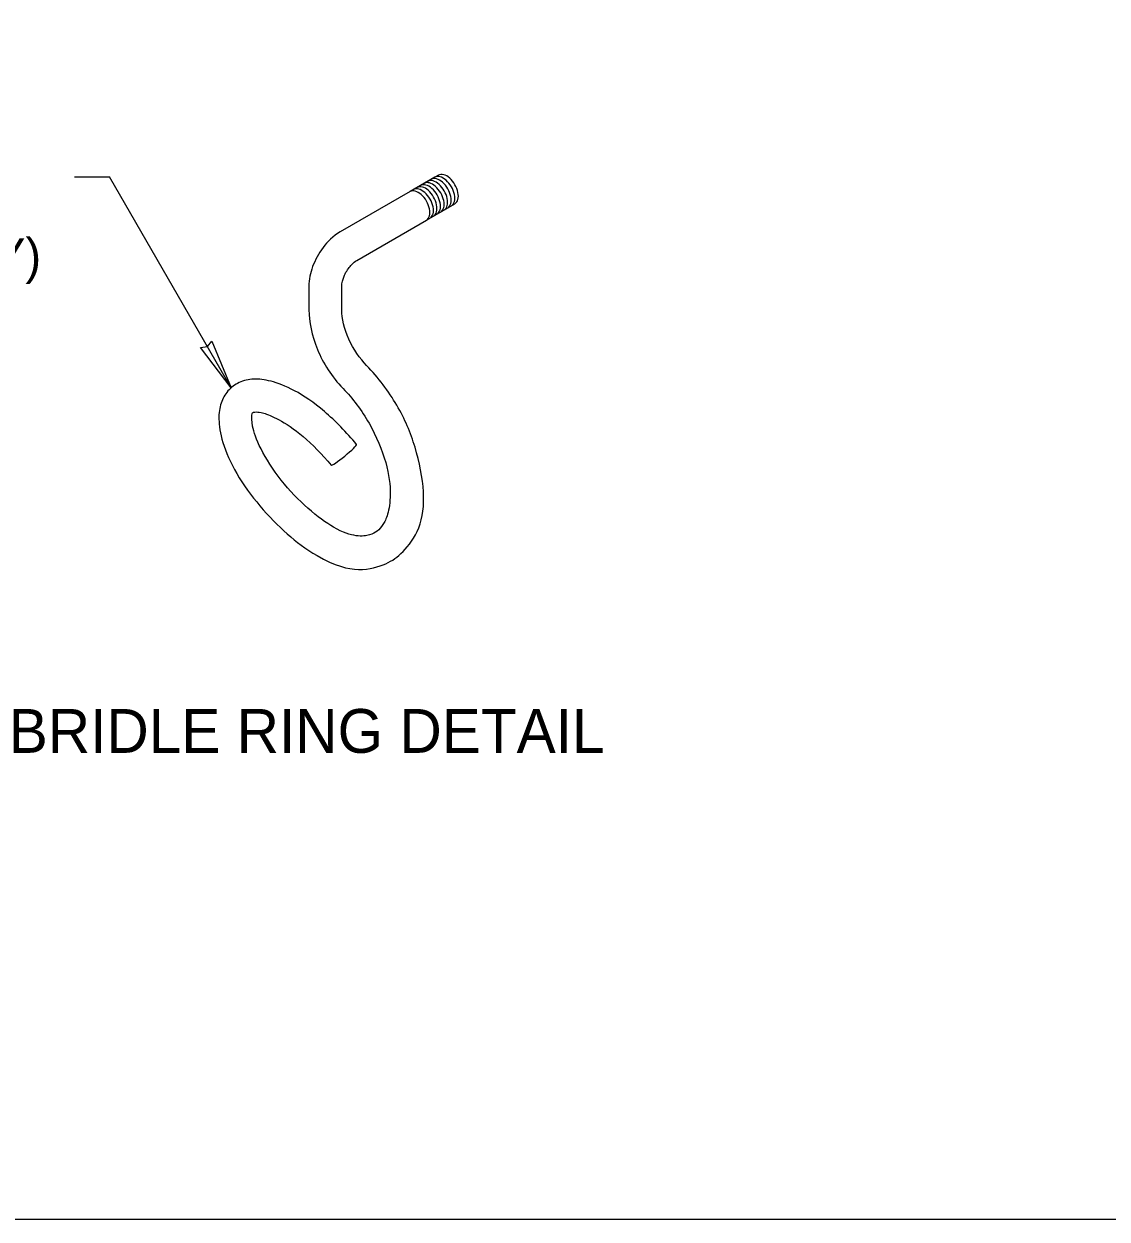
# Model space of a CAD drawing. Extents: x 99862 to 103151, y 100000 to 105076.
# Drawn here: x 101110 to 101605, y 103000 to 103545 of the extents above; entities that cross this region are included whole.
import ezdxf

# ---------------------------------------------------------------- set-up
doc = ezdxf.new("R2010")
doc.units = 0
for name, color, linetype in [('Level 1', 7, 'Continuous'), ('Level 15', 7, 'Continuous'), ('Level 20', 7, 'Continuous'), ('Level 8', 7, 'Continuous')]:
    doc.layers.add(name, color=color, linetype=linetype)

msp = doc.modelspace()

# ---------------------------------------------------------------- linework, layer by layer
at = {"layer": 'Level 1'}
msp.add_lwpolyline([(99862, 102999.5), (103151, 102999.5), (103151, 105075.5), (99862, 105075.5)], close=True, dxfattribs=at)
at = {"layer": 'Level 15'}
for p in [(101133.54, 103475.08), (101205.08, 103378.87)]:
    msp.add_line(p, (101149.54, 103475.08), dxfattribs=at)
msp.add_lwpolyline([(101205.08, 103378.87), (101191.08, 103397.15), (101194.19, 103397.73), (101196.25, 103400.14)], close=True, dxfattribs=at)
at = {"layer": 'Level 8'}
for p, q in [((101298.05, 103474.89), (101286.68, 103468.33)), ((101299.67, 103475.83), (101298.05, 103474.89)), ((101286.68, 103468.33), (101254.86, 103449.95)), ((101294.18, 103455.33), (101307.17, 103462.83)), ((101262.36, 103436.96), (101294.18, 103455.33)), ((101240.51, 103425.09), (101240.51, 103414.35)), ((101255.51, 103414.35), (101255.51, 103425.09))]:
    msp.add_line(p, q, dxfattribs=at)
for centre, major_axis, ratio, start_param, end_param in [((101303.42, 103469.33), (3.75, -6.5), 0.57735, 6.283112, 9.424778), ((101295.3, 103464.64), (3.75, -6.5), 0.57735, 6.283112, 9.424778), ((101296.93, 103465.58), (3.75, -6.5), 0.57735, 6.283112, 9.424778), ((101298.55, 103466.52), (3.75, -6.5), 0.57735, 6.283112, 9.424778), ((101300.17, 103467.45), (3.75, -6.5), 0.57735, 6.283112, 9.424778), ((101301.8, 103468.39), (3.75, -6.5), 0.57735, 6.283112, 9.424778), ((101290.43, 103461.83), (3.75, -6.5), 0.57735, 6.283112, 9.424778), ((101290.43, 103461.83), (3.75, -6.5), 0.57735, 3.141593, 3.141605), ((101292.06, 103462.77), (3.75, -6.5), 0.57735, 6.283112, 9.424778), ((101293.68, 103463.7), (3.75, -6.5), 0.57735, 6.283112, 9.424778), ((101248.01, 103414.35), (7.5, 0), 0.57735, 3.141593, 3.141703), ((101256.45, 103348.22), (5.81, 4.74), 0.091752, 3.1416, 6.283185), ((101256.45, 103348.22), (5.81, 4.74), 0.091752, 3.141585, 3.1416)]:
    msp.add_ellipse(centre, major_axis=major_axis, ratio=ratio, start_param=start_param, end_param=end_param, dxfattribs=at)
for points in [[(101254.86, 103449.95), (101251.44, 103447.98), (101246.61, 103443.24), (101241.71, 103433.99), (101240.51, 103428.3), (101240.51, 103425.09)], [(101255.51, 103425.09), (101255.5, 103426.51), (101256.52, 103430.46), (101259.77, 103435.05), (101261.65, 103436.56), (101262.36, 103436.96)], [(101240.51, 103414.35), (101240.51, 103409.12), (101243.16, 103396.14), (101250.89, 103383.89), (101256.13, 103378.51)], [(101266.88, 103388.97), (101263.82, 103392.12), (101257.83, 103400.86), (101255.5, 103410.45), (101255.51, 103414.35)], [(101244.26, 103302.24), (101252.45, 103297.51), (101263.94, 103294.56), (101276.63, 103298.45), (101283.13, 103302.99), (101291.7, 103314.11), (101293.9, 103330.43), (101289.53, 103352.26), (101281.74, 103370.73), (101272.15, 103383.56), (101266.88, 103388.97)], [(101262.26, 103352.96), (101257.77, 103358.45), (101247.37, 103369.07), (101233.45, 103378.37), (101222.74, 103382.3), (101215.2, 103383.17), (101208.49, 103381.61), (101203.24, 103377.64), (101200.07, 103371.98), (101199.05, 103365.08), (101200.44, 103354.53), (101206.83, 103339.68), (101217.91, 103324.6), (101230.71, 103311.53), (101238.94, 103305.31), (101244.26, 103302.24)], [(101256.13, 103378.51), (101260.49, 103374.03), (101268.72, 103363.03), (101276.62, 103344.04), (101278.18, 103329.34), (101276.51, 103320.43), (101274.39, 103316.12), (101271.78, 103313.28), (101268.71, 103311.53), (101262.73, 103310.69), (101256.15, 103312.7), (101251.76, 103315.23)], [(101251.76, 103315.23), (101248.42, 103317.16), (101240.1, 103323.12), (101227.45, 103336.29), (101217.57, 103351.71), (101214.26, 103362.27), (101214.44, 103366.91), (101214.96, 103367.6), (101214.83, 103367.49), (101215.13, 103367.66), (101216.32, 103367.86), (101219.2, 103367.58), (101226.14, 103365.06), (101237.52, 103357.61), (101246.61, 103348.4), (101250.63, 103343.47)]]:
    msp.add_open_spline(points, degree=3, dxfattribs=at)

# ---------------------------------------------------------------- texts
at = {"layer": 'Level 20'}
for s, height, p in [('COMMERCIALLY)', 16, (100939.97, 103431.07)), ('BRIDLE RING DETAIL', 20, (101103.52, 103212.24))]:
    msp.add_text(s, height=height, dxfattribs=at).set_placement(p)

doc.saveas('drawing.dxf')
